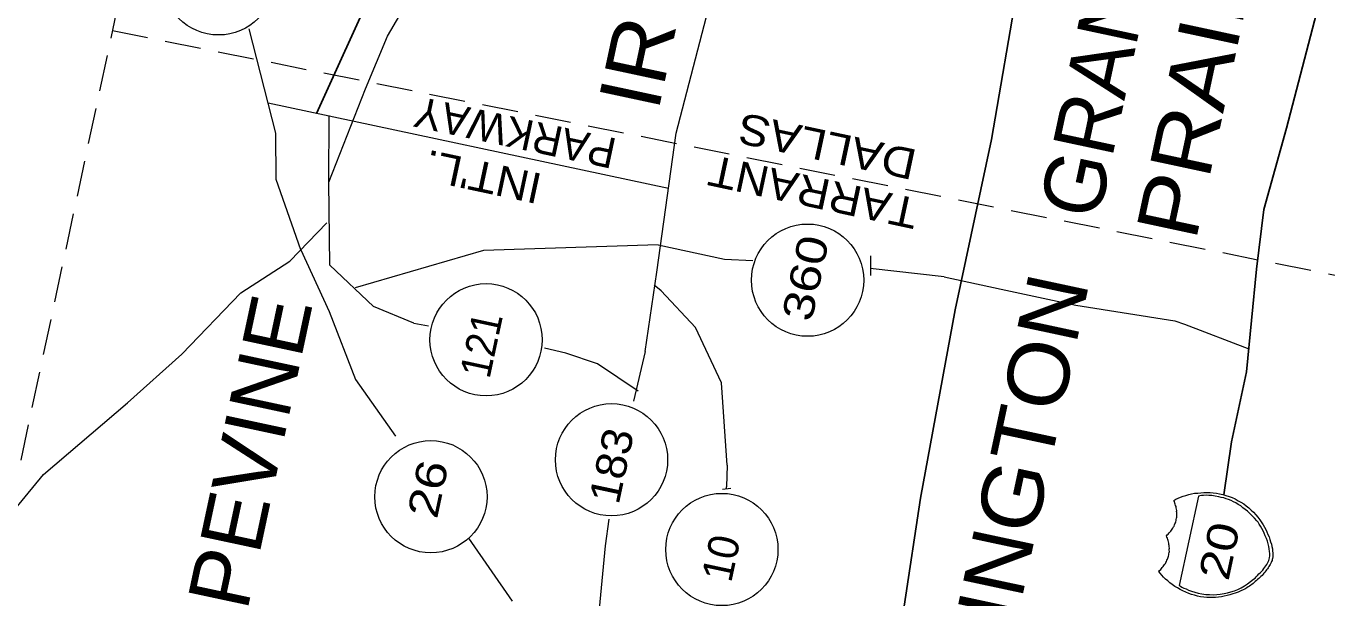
# Model space of a CAD drawing. Extents: x 2363411 to 2369126, y 6976878 to 6988319.
# Drawn here: x 2368157 to 2368374.1, y 6988086.1 to 6988181.5 of the extents above; entities that cross this region are included whole.
import ezdxf

# ---------------------------------------------------------------- set-up
doc = ezdxf.new("R2010")
doc.units = 0
doc.header["$LTSCALE"] = 2
doc.linetypes.add('MEDIUM_DASHED', pattern=[4.5, 3, -1.5])
doc.layers.add('62', color=7, linetype='Continuous', lineweight=13)
doc.layers.add('63', color=7, linetype='Continuous', lineweight=13)

msp = doc.modelspace()

# ---------------------------------------------------------------- linework, layer by layer
at = {"layer": '62', "linetype": 'MEDIUM_DASHED'}
for p, q in [((2368191.192, 6988273.413), (2368097.525, 6987835.044)), ((2368171.397, 6988180.77), (2368446.955, 6988125.71))]:
    msp.add_line(p, q, dxfattribs=at)
at = {"layer": '62'}
for p, q in [((2368264.201, 6988154.406), (2368197.392, 6988168.681)), ((2368207.501, 6988155.476), (2368207.555, 6988166.604)), ((2368200.988, 6988142.326), (2368207.177, 6988148.687)), ((2368262.497, 6988145.038), (2368273.589, 6988142.67)), ((2368273.589, 6988142.67), (2368278.319, 6988142.416)), ((2368297.967, 6988139.921), (2368298.019, 6988143.178)), ((2368310.25, 6988139.69), (2368297.876, 6988141.112)), ((2368262.976, 6988137.364), (2368261.841, 6988138.298)), ((2368221.687, 6988131.944), (2368224.181, 6988131.55)), ((2368348.761, 6988132.336), (2368350.347, 6988131.791)), ((2368350.347, 6988131.791), (2368361.067, 6988127.68)), ((2368247.086, 6988126.977), (2368243.534, 6988127.806)), ((2368260.308, 6988127.259), (2368258.373, 6988118.952)), ((2368211.956, 6988122.589), (2368218.66, 6988113.146)), ((2368274.018, 6988108.291), (2368273.914, 6988104.677)), ((2368273.228, 6988104.271), (2368274.642, 6988104.429)), ((2368273.888, 6988104.337), (2368273.914, 6988104.677)), ((2368253.722, 6988094.819), (2368254.327, 6988099.266)), ((2368238.175, 6988085.6), (2368230.895, 6988096.107))]:
    msp.add_line(p, q, dxfattribs=at)
for points in [[(2368260.308, 6988127.259), (2368262.282, 6988140.48), (2368265.488, 6988163.656), (2368270.883, 6988184.388), (2368274.562, 6988198.165), (2368278.528, 6988215.751), (2368278.264, 6988226.37), (2368273.748, 6988239.482), (2368269.937, 6988253.851), (2368269.65, 6988258.007)], [(2368213.641, 6988171.077), (2368217.313, 6988179.866), (2368224.076, 6988191.375), (2368232.244, 6988198.902)], [(2368202.866, 6988144.226), (2368198.738, 6988155.922), (2368198.667, 6988163.666), (2368194.245, 6988181.089)], [(2368207.718, 6988141.627), (2368207.501, 6988155.476), (2368213.641, 6988171.077)], [(2368202.866, 6988144.226), (2368207.593, 6988133.943), (2368211.956, 6988122.589)], [(2368262.497, 6988145.038), (2368233.343, 6988144.064), (2368211.925, 6988137.85)], [(2368072.165, 6987905.558), (2368069.558, 6987916.954), (2368070.74, 6987931.312), (2368081.321, 6987945.504), (2368084.53, 6987956.002), (2368094.219, 6987967.853), (2368100.778, 6987976.045), (2368105.415, 6987983.319), (2368109.901, 6987993.976), (2368112.685, 6988002.816), (2368115.664, 6988014.605), (2368118.107, 6988028.624), (2368124.138, 6988045.861), (2368127.394, 6988057.221), (2368131.763, 6988070.025), (2368141.291, 6988083.154), (2368150.678, 6988095.548), (2368159.881, 6988106.746), (2368173.939, 6988118.699), (2368182.972, 6988126.824), (2368192.837, 6988137.028), (2368200.988, 6988142.326)], [(2368221.687, 6988131.944), (2368214.964, 6988134.738), (2368207.718, 6988141.627)], [(2368310.25, 6988139.69), (2368319.755, 6988137.657), (2368332.234, 6988134.992), (2368348.761, 6988132.336)], [(2368274.018, 6988108.291), (2368273.088, 6988122.021), (2368268.734, 6988131.258), (2368262.976, 6988137.364)], [(2368259.14, 6988120.606), (2368252.36, 6988125.161), (2368247.086, 6988126.977)], [(2368347.913, 6988097.126), (2368348.065, 6988097.3), (2368348.192, 6988097.459), (2368348.295, 6988097.619), (2368348.425, 6988097.8), (2368348.49, 6988097.995), (2368348.611, 6988098.129), (2368348.677, 6988098.323), (2368348.757, 6988098.488), (2368348.842, 6988098.676), (2368348.902, 6988098.85), (2368348.944, 6988099.047), (2368348.986, 6988099.245), (2368349.024, 6988099.421), (2368349.061, 6988099.597), (2368349.082, 6988099.799), (2368349.076, 6988099.986), (2368349.072, 6988100.171), (2368349.091, 6988100.374), (2368349.041, 6988100.569), (2368349.056, 6988100.749), (2368349.009, 6988100.966), (2368348.986, 6988101.177), (2368348.936, 6988101.374), (2368348.864, 6988101.572), (2368348.813, 6988101.767), (2368348.739, 6988101.966), (2368348.654, 6988102.216), (2368348.582, 6988102.413), (2368348.922, 6988102.596), (2368349.307, 6988102.79), (2368349.709, 6988102.956), (2368350.154, 6988103.092), (2368350.597, 6988103.226), (2368351.068, 6988103.379), (2368351.527, 6988103.488), (2368352.033, 6988103.588), (2368352.549, 6988103.639), (2368353.065, 6988103.689), (2368353.604, 6988103.735), (2368354.135, 6988103.736), (2368354.66, 6988103.718), (2368355.158, 6988103.677), (2368355.673, 6988103.616), (2368356.183, 6988103.529), (2368356.729, 6988103.388), (2368357.271, 6988103.228), (2368357.805, 6988103.046), (2368358.297, 6988102.869), (2368358.802, 6988102.647), (2368359.294, 6988102.358), (2368359.766, 6988102.095), (2368360.24, 6988101.834), (2368360.654, 6988101.515), (2368361.081, 6988101.15), (2368361.491, 6988100.806), (2368361.871, 6988100.426), (2368362.267, 6988100.021), (2368362.614, 6988099.601), (2368362.935, 6988099.164), (2368363.269, 6988098.678), (2368363.491, 6988098.309), (2368363.708, 6988097.94), (2368363.926, 6988097.55), (2368364.119, 6988097.163), (2368364.28, 6988096.738), (2368364.464, 6988096.306), (2368364.609, 6988095.907), (2368364.732, 6988095.512), (2368364.855, 6988095.12), (2368364.955, 6988094.728), (2368365.034, 6988094.343), (2368365.063, 6988093.944), (2368365.092, 6988093.64), (2368365.086, 6988093.295), (2368365.092, 6988092.996), (2368365.035, 6988092.73)], [(2368365.035, 6988092.73), (2368364.998, 6988092.555), (2368364.965, 6988092.401), (2368364.878, 6988092.215), (2368364.823, 6988092.063), (2368364.746, 6988091.92), (2368364.639, 6988091.734), (2368364.551, 6988091.547), (2368364.443, 6988091.363), (2368364.313, 6988091.184), (2368364.183, 6988091.004), (2368364.049, 6988090.803), (2368363.922, 6988090.646), (2368363.764, 6988090.449), (2368363.612, 6988090.273), (2368363.461, 6988090.1), (2368363.304, 6988089.903), (2368363.107, 6988089.738), (2368362.927, 6988089.546), (2368362.749, 6988089.355), (2368362.559, 6988089.209), (2368362.384, 6988089.04), (2368362.166, 6988088.882), (2368361.987, 6988088.689), (2368361.798, 6988088.568), (2368361.602, 6988088.403), (2368361.411, 6988088.258), (2368361.193, 6988088.1), (2368360.985, 6988087.985), (2368360.771, 6988087.845), (2368360.583, 6988087.723), (2368360.401, 6988087.627), (2368360.169, 6988087.511), (2368359.757, 6988087.303), (2368359.305, 6988087.123), (2368358.831, 6988086.95), (2368358.408, 6988086.807), (2368357.939, 6988086.654), (2368357.452, 6988086.529), (2368356.993, 6988086.419), (2368356.513, 6988086.337), (2368356.042, 6988086.276), (2368355.546, 6988086.223), (2368355.061, 6988086.21), (2368354.574, 6988086.199), (2368354.073, 6988086.214), (2368353.579, 6988086.275), (2368353.041, 6988086.341), (2368352.53, 6988086.429), (2368352.033, 6988086.581), (2368351.536, 6988086.734), (2368351.063, 6988086.882), (2368350.58, 6988087.1), (2368350.097, 6988087.319), (2368349.62, 6988087.556), (2368349.168, 6988087.815), (2368348.718, 6988088.072), (2368348.296, 6988088.369), (2368347.922, 6988088.655), (2368347.55, 6988088.966), (2368347.205, 6988089.293), (2368346.861, 6988089.618), (2368346.556, 6988089.917), (2368346.284, 6988090.251), (2368346.049, 6988090.555), (2368346.201, 6988090.729), (2368346.375, 6988090.9), (2368346.528, 6988091.072), (2368346.649, 6988091.21), (2368346.802, 6988091.382), (2368346.928, 6988091.539), (2368347.034, 6988091.723), (2368347.165, 6988091.903), (2368347.226, 6988092.074), (2368347.351, 6988092.232), (2368347.415, 6988092.427), (2368347.496, 6988092.591), (2368347.582, 6988092.777), (2368347.641, 6988092.951), (2368347.679, 6988093.129), (2368347.728, 6988093.347), (2368347.759, 6988093.5), (2368347.803, 6988093.7), (2368347.819, 6988093.88), (2368347.816, 6988094.088), (2368347.812, 6988094.274), (2368347.826, 6988094.456), (2368347.781, 6988094.672), (2368347.799, 6988094.872), (2368347.744, 6988095.046), (2368347.722, 6988095.259), (2368347.677, 6988095.475), (2368347.608, 6988095.699), (2368347.552, 6988095.87), (2368347.486, 6988096.091), (2368347.392, 6988096.295), (2368347.323, 6988096.518), (2368347.47, 6988096.669), (2368347.636, 6988096.793), (2368347.788, 6988096.971), (2368347.913, 6988097.126)], [(2368250.441, 6988058.681), (2368252.01, 6988077.326), (2368253.722, 6988094.819)]]:
    msp.add_lwpolyline(points, dxfattribs=at)
at = {"layer": '62', "lineweight": 25}
for points in [[(2368327.726, 6988245.598), (2368326.234, 6988232.478), (2368324.804, 6988212.33), (2368322.527, 6988188.217), (2368318.14, 6988162.623), (2368312.07, 6988134.214), (2368306.258, 6988102.807), (2368303.557, 6988084.792)], [(2368398.516, 6988230.474), (2368388.619, 6988219.148), (2368381.474, 6988203.373), (2368373.402, 6988187.563), (2368367.395, 6988164.505), (2368363.602, 6988150.954), (2368362.368, 6988140.978), (2368360.68, 6988123.828), (2368358.194, 6988112.187), (2368356.9, 6988103.329)], [(2368230.132, 6988215.091), (2368215.269, 6988188.493), (2368205.489, 6988166.951)]]:
    msp.add_lwpolyline(points, dxfattribs=at)
at = {"layer": '62'}
msp.add_lwpolyline([(2368352.671, 6988103.129), (2368349.486, 6988088.231), (2368349.694, 6988088.117), (2368349.933, 6988087.95), (2368350.221, 6988087.796), (2368350.626, 6988087.642), (2368351.021, 6988087.443), (2368351.508, 6988087.247), (2368352.049, 6988087.084), (2368352.639, 6988086.936), (2368353.259, 6988086.826), (2368353.884, 6988086.737), (2368354.519, 6988086.694), (2368355.115, 6988086.683), (2368355.742, 6988086.708), (2368356.329, 6988086.767), (2368356.948, 6988086.866), (2368357.528, 6988086.996), (2368358.091, 6988087.153), (2368358.687, 6988087.349), (2368359.241, 6988087.574), (2368359.803, 6988087.847), (2368360.356, 6988088.164), (2368360.861, 6988088.492), (2368361.379, 6988088.866), (2368361.858, 6988089.269), (2368362.124, 6988089.443), (2368362.335, 6988089.672), (2368362.561, 6988089.877), (2368362.776, 6988090.132), (2368362.98, 6988090.318), (2368363.21, 6988090.545), (2368363.399, 6988090.782), (2368363.592, 6988091.038), (2368363.753, 6988091.257), (2368363.92, 6988091.497), (2368364.087, 6988091.74), (2368364.201, 6988091.945), (2368364.317, 6988092.171), (2368364.41, 6988092.383), (2368364.504, 6988092.616), (2368364.552, 6988092.835), (2368364.595, 6988093.149), (2368364.608, 6988093.537), (2368364.548, 6988093.895), (2368364.504, 6988094.34), (2368364.453, 6988094.746), (2368364.312, 6988095.166), (2368364.178, 6988095.608), (2368364.022, 6988096.057), (2368363.84, 6988096.509), (2368363.652, 6988096.919), (2368363.463, 6988097.326), (2368363.253, 6988097.738), (2368363.06, 6988098.125), (2368362.829, 6988098.451), (2368362.623, 6988098.773), (2368362.399, 6988099.025), (2368362.03, 6988099.45), (2368361.633, 6988099.856), (2368361.277, 6988100.232), (2368360.849, 6988100.6), (2368360.477, 6988100.908), (2368360.102, 6988101.195), (2368359.727, 6988101.484), (2368359.32, 6988101.73), (2368358.911, 6988101.979), (2368358.543, 6988102.197), (2368358.123, 6988102.379), (2368357.72, 6988102.532), (2368357.312, 6988102.667), (2368356.907, 6988102.823), (2368356.49, 6988102.912), (2368356.076, 6988103.023), (2368355.477, 6988103.128), (2368354.917, 6988103.203), (2368354.397, 6988103.242), (2368353.965, 6988103.267), (2368353.524, 6988103.245), (2368353.192, 6988103.201), (2368352.91, 6988103.17)], close=True, dxfattribs=at)
for centre in [(2368189.128, 6988189.404), (2368287.443, 6988139.144), (2368233.765, 6988129.206), (2368254.712, 6988109.186), (2368224.564, 6988103.023), (2368273.134, 6988094.221)]:
    msp.add_circle(centre, 9.364, dxfattribs=at)
at = {"layer": '63', "linetype": 'MEDIUM_DASHED'}
for p, q in [((2368191.192, 6988273.413), (2368097.525, 6987835.044)), ((2368171.397, 6988180.77), (2368446.955, 6988125.71))]:
    msp.add_line(p, q, dxfattribs=at)
at = {"layer": '63'}
for p, q in [((2368264.201, 6988154.406), (2368197.392, 6988168.681)), ((2368207.501, 6988155.476), (2368207.555, 6988166.604)), ((2368200.988, 6988142.326), (2368207.177, 6988148.687)), ((2368262.497, 6988145.038), (2368273.589, 6988142.67)), ((2368273.589, 6988142.67), (2368278.319, 6988142.416)), ((2368297.967, 6988139.921), (2368298.019, 6988143.178)), ((2368310.25, 6988139.69), (2368297.876, 6988141.112)), ((2368262.976, 6988137.364), (2368261.841, 6988138.298)), ((2368221.687, 6988131.944), (2368224.181, 6988131.55)), ((2368348.761, 6988132.336), (2368350.347, 6988131.791)), ((2368350.347, 6988131.791), (2368361.067, 6988127.68)), ((2368247.086, 6988126.977), (2368243.534, 6988127.806)), ((2368260.308, 6988127.259), (2368258.373, 6988118.952)), ((2368211.956, 6988122.589), (2368218.66, 6988113.146)), ((2368274.018, 6988108.291), (2368273.914, 6988104.677)), ((2368273.228, 6988104.271), (2368274.642, 6988104.429)), ((2368273.888, 6988104.337), (2368273.914, 6988104.677)), ((2368253.722, 6988094.819), (2368254.327, 6988099.266)), ((2368238.175, 6988085.6), (2368230.895, 6988096.107))]:
    msp.add_line(p, q, dxfattribs=at)
for points in [[(2368260.308, 6988127.259), (2368262.282, 6988140.48), (2368265.488, 6988163.656), (2368270.883, 6988184.388), (2368274.562, 6988198.165), (2368278.528, 6988215.751), (2368278.264, 6988226.37), (2368273.748, 6988239.482), (2368269.937, 6988253.851), (2368269.65, 6988258.007)], [(2368213.641, 6988171.077), (2368217.313, 6988179.866), (2368224.076, 6988191.375), (2368232.244, 6988198.902)], [(2368202.866, 6988144.226), (2368198.738, 6988155.922), (2368198.667, 6988163.666), (2368194.245, 6988181.089)], [(2368207.718, 6988141.627), (2368207.501, 6988155.476), (2368213.641, 6988171.077)], [(2368202.866, 6988144.226), (2368207.593, 6988133.943), (2368211.956, 6988122.589)], [(2368262.497, 6988145.038), (2368233.343, 6988144.064), (2368211.925, 6988137.85)], [(2368072.165, 6987905.558), (2368069.558, 6987916.954), (2368070.74, 6987931.312), (2368081.321, 6987945.504), (2368084.53, 6987956.002), (2368094.219, 6987967.853), (2368100.778, 6987976.045), (2368105.415, 6987983.319), (2368109.901, 6987993.976), (2368112.685, 6988002.816), (2368115.664, 6988014.605), (2368118.107, 6988028.624), (2368124.138, 6988045.861), (2368127.394, 6988057.221), (2368131.763, 6988070.025), (2368141.291, 6988083.154), (2368150.678, 6988095.548), (2368159.881, 6988106.746), (2368173.939, 6988118.699), (2368182.972, 6988126.824), (2368192.837, 6988137.028), (2368200.988, 6988142.326)], [(2368221.687, 6988131.944), (2368214.964, 6988134.738), (2368207.718, 6988141.627)], [(2368310.25, 6988139.69), (2368319.755, 6988137.657), (2368332.234, 6988134.992), (2368348.761, 6988132.336)], [(2368274.018, 6988108.291), (2368273.088, 6988122.021), (2368268.734, 6988131.258), (2368262.976, 6988137.364)], [(2368259.14, 6988120.606), (2368252.36, 6988125.161), (2368247.086, 6988126.977)], [(2368347.913, 6988097.126), (2368348.065, 6988097.3), (2368348.192, 6988097.459), (2368348.295, 6988097.619), (2368348.425, 6988097.8), (2368348.49, 6988097.995), (2368348.611, 6988098.129), (2368348.677, 6988098.323), (2368348.757, 6988098.488), (2368348.842, 6988098.676), (2368348.902, 6988098.85), (2368348.944, 6988099.047), (2368348.986, 6988099.245), (2368349.024, 6988099.421), (2368349.061, 6988099.597), (2368349.082, 6988099.799), (2368349.076, 6988099.986), (2368349.072, 6988100.171), (2368349.091, 6988100.374), (2368349.041, 6988100.569), (2368349.056, 6988100.749), (2368349.009, 6988100.966), (2368348.986, 6988101.177), (2368348.936, 6988101.374), (2368348.864, 6988101.572), (2368348.813, 6988101.767), (2368348.739, 6988101.966), (2368348.654, 6988102.216), (2368348.582, 6988102.413), (2368348.922, 6988102.596), (2368349.307, 6988102.79), (2368349.709, 6988102.956), (2368350.154, 6988103.092), (2368350.597, 6988103.226), (2368351.068, 6988103.379), (2368351.527, 6988103.488), (2368352.033, 6988103.588), (2368352.549, 6988103.639), (2368353.065, 6988103.689), (2368353.604, 6988103.735), (2368354.135, 6988103.736), (2368354.66, 6988103.718), (2368355.158, 6988103.677), (2368355.673, 6988103.616), (2368356.183, 6988103.529), (2368356.729, 6988103.388), (2368357.271, 6988103.228), (2368357.805, 6988103.046), (2368358.297, 6988102.869), (2368358.802, 6988102.647), (2368359.294, 6988102.358), (2368359.766, 6988102.095), (2368360.24, 6988101.834), (2368360.654, 6988101.515), (2368361.081, 6988101.15), (2368361.491, 6988100.806), (2368361.871, 6988100.426), (2368362.267, 6988100.021), (2368362.614, 6988099.601), (2368362.935, 6988099.164), (2368363.269, 6988098.678), (2368363.491, 6988098.309), (2368363.708, 6988097.94), (2368363.926, 6988097.55), (2368364.119, 6988097.163), (2368364.28, 6988096.738), (2368364.464, 6988096.306), (2368364.609, 6988095.907), (2368364.732, 6988095.512), (2368364.855, 6988095.12), (2368364.955, 6988094.728), (2368365.034, 6988094.343), (2368365.063, 6988093.944), (2368365.092, 6988093.64), (2368365.086, 6988093.295), (2368365.092, 6988092.996), (2368365.035, 6988092.73)], [(2368365.035, 6988092.73), (2368364.998, 6988092.555), (2368364.965, 6988092.401), (2368364.878, 6988092.215), (2368364.823, 6988092.063), (2368364.746, 6988091.92), (2368364.639, 6988091.734), (2368364.551, 6988091.547), (2368364.443, 6988091.363), (2368364.313, 6988091.184), (2368364.183, 6988091.004), (2368364.049, 6988090.803), (2368363.922, 6988090.646), (2368363.764, 6988090.449), (2368363.612, 6988090.273), (2368363.461, 6988090.1), (2368363.304, 6988089.903), (2368363.107, 6988089.738), (2368362.927, 6988089.546), (2368362.749, 6988089.355), (2368362.559, 6988089.209), (2368362.384, 6988089.04), (2368362.166, 6988088.882), (2368361.987, 6988088.689), (2368361.798, 6988088.568), (2368361.602, 6988088.403), (2368361.411, 6988088.258), (2368361.193, 6988088.1), (2368360.985, 6988087.985), (2368360.771, 6988087.845), (2368360.583, 6988087.723), (2368360.401, 6988087.627), (2368360.169, 6988087.511), (2368359.757, 6988087.303), (2368359.305, 6988087.123), (2368358.831, 6988086.95), (2368358.408, 6988086.807), (2368357.939, 6988086.654), (2368357.452, 6988086.529), (2368356.993, 6988086.419), (2368356.513, 6988086.337), (2368356.042, 6988086.276), (2368355.546, 6988086.223), (2368355.061, 6988086.21), (2368354.574, 6988086.199), (2368354.073, 6988086.214), (2368353.579, 6988086.275), (2368353.041, 6988086.341), (2368352.53, 6988086.429), (2368352.033, 6988086.581), (2368351.536, 6988086.734), (2368351.063, 6988086.882), (2368350.58, 6988087.1), (2368350.097, 6988087.319), (2368349.62, 6988087.556), (2368349.168, 6988087.815), (2368348.718, 6988088.072), (2368348.296, 6988088.369), (2368347.922, 6988088.655), (2368347.55, 6988088.966), (2368347.205, 6988089.293), (2368346.861, 6988089.618), (2368346.556, 6988089.917), (2368346.284, 6988090.251), (2368346.049, 6988090.555), (2368346.201, 6988090.729), (2368346.375, 6988090.9), (2368346.528, 6988091.072), (2368346.649, 6988091.21), (2368346.802, 6988091.382), (2368346.928, 6988091.539), (2368347.034, 6988091.723), (2368347.165, 6988091.903), (2368347.226, 6988092.074), (2368347.351, 6988092.232), (2368347.415, 6988092.427), (2368347.496, 6988092.591), (2368347.582, 6988092.777), (2368347.641, 6988092.951), (2368347.679, 6988093.129), (2368347.728, 6988093.347), (2368347.759, 6988093.5), (2368347.803, 6988093.7), (2368347.819, 6988093.88), (2368347.816, 6988094.088), (2368347.812, 6988094.274), (2368347.826, 6988094.456), (2368347.781, 6988094.672), (2368347.799, 6988094.872), (2368347.744, 6988095.046), (2368347.722, 6988095.259), (2368347.677, 6988095.475), (2368347.608, 6988095.699), (2368347.552, 6988095.87), (2368347.486, 6988096.091), (2368347.392, 6988096.295), (2368347.323, 6988096.518), (2368347.47, 6988096.669), (2368347.636, 6988096.793), (2368347.788, 6988096.971), (2368347.913, 6988097.126)], [(2368250.441, 6988058.681), (2368252.01, 6988077.326), (2368253.722, 6988094.819)]]:
    msp.add_lwpolyline(points, dxfattribs=at)
at = {"layer": '63', "lineweight": 25}
for points in [[(2368327.726, 6988245.598), (2368326.234, 6988232.478), (2368324.804, 6988212.33), (2368322.527, 6988188.217), (2368318.14, 6988162.623), (2368312.07, 6988134.214), (2368306.258, 6988102.807), (2368303.557, 6988084.792)], [(2368398.516, 6988230.474), (2368388.619, 6988219.148), (2368381.474, 6988203.373), (2368373.402, 6988187.563), (2368367.395, 6988164.505), (2368363.602, 6988150.954), (2368362.368, 6988140.978), (2368360.68, 6988123.828), (2368358.194, 6988112.187), (2368356.9, 6988103.329)], [(2368230.132, 6988215.091), (2368215.269, 6988188.493), (2368205.489, 6988166.951)]]:
    msp.add_lwpolyline(points, dxfattribs=at)
at = {"layer": '63'}
msp.add_lwpolyline([(2368352.671, 6988103.129), (2368349.486, 6988088.231), (2368349.694, 6988088.117), (2368349.933, 6988087.95), (2368350.221, 6988087.796), (2368350.626, 6988087.642), (2368351.021, 6988087.443), (2368351.508, 6988087.247), (2368352.049, 6988087.084), (2368352.639, 6988086.936), (2368353.259, 6988086.826), (2368353.884, 6988086.737), (2368354.519, 6988086.694), (2368355.115, 6988086.683), (2368355.742, 6988086.708), (2368356.329, 6988086.767), (2368356.948, 6988086.866), (2368357.528, 6988086.996), (2368358.091, 6988087.153), (2368358.687, 6988087.349), (2368359.241, 6988087.574), (2368359.803, 6988087.847), (2368360.356, 6988088.164), (2368360.861, 6988088.492), (2368361.379, 6988088.866), (2368361.858, 6988089.269), (2368362.124, 6988089.443), (2368362.335, 6988089.672), (2368362.561, 6988089.877), (2368362.776, 6988090.132), (2368362.98, 6988090.318), (2368363.21, 6988090.545), (2368363.399, 6988090.782), (2368363.592, 6988091.038), (2368363.753, 6988091.257), (2368363.92, 6988091.497), (2368364.087, 6988091.74), (2368364.201, 6988091.945), (2368364.317, 6988092.171), (2368364.41, 6988092.383), (2368364.504, 6988092.616), (2368364.552, 6988092.835), (2368364.595, 6988093.149), (2368364.608, 6988093.537), (2368364.548, 6988093.895), (2368364.504, 6988094.34), (2368364.453, 6988094.746), (2368364.312, 6988095.166), (2368364.178, 6988095.608), (2368364.022, 6988096.057), (2368363.84, 6988096.509), (2368363.652, 6988096.919), (2368363.463, 6988097.326), (2368363.253, 6988097.738), (2368363.06, 6988098.125), (2368362.829, 6988098.451), (2368362.623, 6988098.773), (2368362.399, 6988099.025), (2368362.03, 6988099.45), (2368361.633, 6988099.856), (2368361.277, 6988100.232), (2368360.849, 6988100.6), (2368360.477, 6988100.908), (2368360.102, 6988101.195), (2368359.727, 6988101.484), (2368359.32, 6988101.73), (2368358.911, 6988101.979), (2368358.543, 6988102.197), (2368358.123, 6988102.379), (2368357.72, 6988102.532), (2368357.312, 6988102.667), (2368356.907, 6988102.823), (2368356.49, 6988102.912), (2368356.076, 6988103.023), (2368355.477, 6988103.128), (2368354.917, 6988103.203), (2368354.397, 6988103.242), (2368353.965, 6988103.267), (2368353.524, 6988103.245), (2368353.192, 6988103.201), (2368352.91, 6988103.17)], close=True, dxfattribs=at)
for centre in [(2368189.128, 6988189.404), (2368287.443, 6988139.144), (2368233.765, 6988129.206), (2368254.712, 6988109.186), (2368224.564, 6988103.023), (2368273.134, 6988094.221)]:
    msp.add_circle(centre, 9.364, dxfattribs=at)

# ---------------------------------------------------------------- texts
at = {"layer": '62'}
for s, height, rotation, width, p in [('IRVING', 10.21, 77.939, 1.1, (2368262.487, 6988167.061)), ('PRAIRIE', 10.21, 77.939, 1.15, (2368352.213, 6988145.474)), ('DALLAS', 5.099, 167.939, 1.15, (2368305.951, 6988160.813)), ("INT'L.", 5.099, 167.939, 1.1, (2368243.405, 6988156.806)), ('TARRANT', 5.099, 167.939, 1.1, (2368306.249, 6988152.626)), ('360', 5.099, 77.939, 1.25, (2368288.089, 6988132.024)), ('ARLINGTON', 10.21, 77.939, 1.1, (2368316.177, 6988053.058)), ('GRAPEVINE', 10.21, 77.939, 1.05, (2368187.388, 6988053.375)), ('121', 5.099, 77.939, 0.95, (2368234.336, 6988122.548)), ('183', 5.099, 77.939, 1.1, (2368255.893, 6988101.534)), ('26', 5.099, 77.939, 1.25, (2368225.564, 6988099.155)), ('20', 5.099, 77.939, 1.25, (2368357.663, 6988088.81))]:
    msp.add_text(s, height=height, rotation=rotation, dxfattribs=dict(at, width=width)).set_placement(p)
for s, height, rotation, p in [('GRAND', 10.21, 77.939, (2368336.018, 6988148.934)), ('PARKWAY', 5.099, 167.939, (2368255.82, 6988162.687)), ('10', 5.099, 77.939, (2368274.678, 6988088.546))]:
    msp.add_text(s, height=height, rotation=rotation, dxfattribs=at).set_placement(p)
at = {"layer": '63'}
for s, height, rotation, width, p in [('IRVING', 10.21, 77.939, 1.1, (2368262.487, 6988167.061)), ('PRAIRIE', 10.21, 77.939, 1.15, (2368352.213, 6988145.474)), ('DALLAS', 5.099, 167.939, 1.15, (2368305.951, 6988160.813)), ("INT'L.", 5.099, 167.939, 1.1, (2368243.405, 6988156.806)), ('TARRANT', 5.099, 167.939, 1.1, (2368306.249, 6988152.626)), ('360', 5.099, 77.939, 1.25, (2368288.089, 6988132.024)), ('ARLINGTON', 10.21, 77.939, 1.1, (2368316.177, 6988053.058)), ('GRAPEVINE', 10.21, 77.939, 1.05, (2368187.388, 6988053.375)), ('121', 5.099, 77.939, 0.95, (2368234.336, 6988122.548)), ('183', 5.099, 77.939, 1.1, (2368255.893, 6988101.534)), ('26', 5.099, 77.939, 1.25, (2368225.564, 6988099.155)), ('20', 5.099, 77.939, 1.25, (2368357.663, 6988088.81))]:
    msp.add_text(s, height=height, rotation=rotation, dxfattribs=dict(at, width=width)).set_placement(p)
for s, height, rotation, p in [('GRAND', 10.21, 77.939, (2368336.018, 6988148.934)), ('PARKWAY', 5.099, 167.939, (2368255.82, 6988162.687)), ('10', 5.099, 77.939, (2368274.678, 6988088.546))]:
    msp.add_text(s, height=height, rotation=rotation, dxfattribs=at).set_placement(p)

doc.saveas('drawing.dxf')
